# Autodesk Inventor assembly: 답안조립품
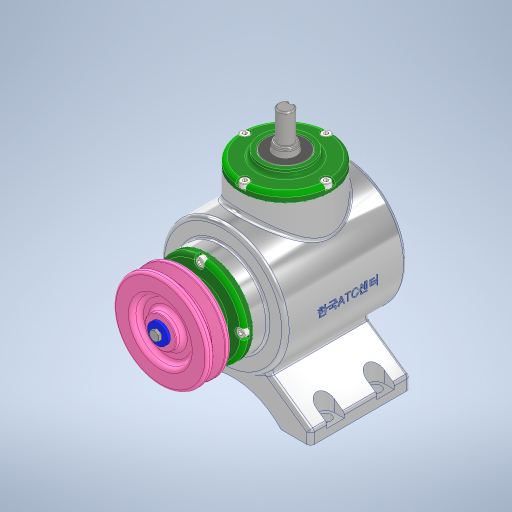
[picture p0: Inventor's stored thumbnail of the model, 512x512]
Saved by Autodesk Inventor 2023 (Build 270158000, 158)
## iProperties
Created: 2023-12
Part Number: 답안조립품
Document SubType Name: Assembly
Designer: asung
Author: asung
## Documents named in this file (17)
- C:\Users\asung\Desktop\731210V1003\답안조립품.iam
- C:\Users\asung\Desktop\731210V1003\본체.ipt
- C:\Users\asung\Desktop\731210V1003\공용부품\베어링 6203.ipt
- C:\Users\asung\Desktop\731210V1003\공용부품\볼트 M4 x 10.ipt
- C:\Users\asung\Desktop\731210V1003\공용부품\오일실 17 x 32 x 8.ipt
- C:\Users\asung\Desktop\731210V1003\공용부품\커버.ipt
- C:\Users\asung\Desktop\731210V1003\공용부품\키 4 x 4 x 14.ipt
- C:\Users\asung\Desktop\731210V1003\공용부품\V-벨트풀리.ipt
- C:\Users\asung\Desktop\731210V1003\공용부품\메인 베벨기어.ipt
- C:\Users\asung\Desktop\731210V1003\공용부품\메인 축.ipt
- 메인 축.ipt
- C:\Users\asung\Desktop\731210V1003\공용부품\서브 베벨기어.ipt
- C:\Users\asung\Desktop\731210V1003\공용부품\서브 축.ipt
- 서브 축.ipt
- C:\Users\asung\Desktop\731210V1003\공용부품\와셔 4 x 16.ipt
- C:\Users\asung\Desktop\731210V1003\공용부품\육각볼트 M4 x 8.ipt
- C:\Users\asung\Desktop\731210V1003\공용부품\키 5 x 5 x 14.ipt
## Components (1 placed, 1 different names)
1. V-벨트풀리:1
